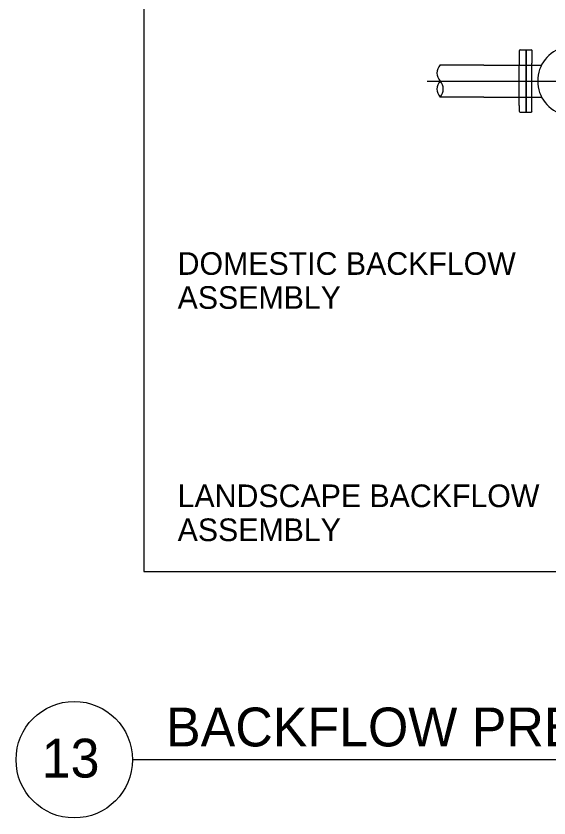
# Model space of a CAD drawing. Extents: x 6710407 to 6714861, y 1868090 to 1871317.
# Drawn here: x 6713621.1 to 6713785.8, y 1869746.3 to 1869994.1 of the extents above; entities that cross this region are included whole.
import ezdxf

# ---------------------------------------------------------------- set-up
doc = ezdxf.new("R2010")
doc.units = 0
doc.layers.add('Nongeo Data(60)', color=7, linetype='Continuous')

msp = doc.modelspace()

# ---------------------------------------------------------------- linework, layer by layer
at = {"layer": 'Nongeo Data(60)'}
for p, q in [((6713660.63, 1870143.75), (6713660.63, 1869916.69)), ((6713776.61, 1869983.35), (6713776.61, 1869978.96)), ((6713776.89, 1869983.63), (6713778.63, 1869983.63)), ((6713778.63, 1869983.63), (6713778.63, 1869969.31)), ((6713778.76, 1869983.62), (6713778.76, 1869969.61)), ((6713778.76, 1869983.62), (6713780.31, 1869983.62)), ((6713780.56, 1869983.37), (6713780.56, 1869979.47)), ((6713765.65, 1869978.93), (6713752.16, 1869978.93)), ((6713765.65, 1869978.93), (6713783.53, 1869978.93)), ((6713776.61, 1869966.46), (6713776.61, 1869978.96)), ((6713780.56, 1869968.49), (6713780.56, 1869979.47)), ((6713748.2, 1869973.99), (6713995.63, 1869973.99)), ((6713765.65, 1869969.02), (6713752.16, 1869969.02)), ((6713765.65, 1869969.02), (6713783.54, 1869969.02)), ((6713778.63, 1869969.31), (6713778.63, 1869964.34)), ((6713778.76, 1869969.61), (6713778.76, 1869964.35)), ((6713780.56, 1869964.6), (6713780.56, 1869968.5)), ((6713776.61, 1869966.46), (6713776.61, 1869964.62)), ((6713776.89, 1869964.34), (6713778.63, 1869964.34)), ((6713778.76, 1869964.35), (6713780.31, 1869964.35)), ((6713660.63, 1869916.69), (6713660.63, 1869822.47)), ((6713660.63, 1869822.47), (6714082.91, 1869822.47)), ((6714108.97, 1869764.3), (6713657.08, 1869764.3))]:
    msp.add_line(p, q, dxfattribs=at)
msp.add_circle((6713639.08, 1869764.3), 18, dxfattribs=at)
for centre, radius, start, end in [((6713793.04, 1869973.99), 10.72, 27.5041, 332.4289), ((6713776.89, 1869983.35), 0.279, 90, 180), ((6713780.31, 1869983.37), 0.257, 0, 90), ((6713754.77, 1869976.46), 3.6, 136.5226, 223.5571), ((6713754.78, 1869971.5), 3.6, 136.461, 223.4594), ((6713749.56, 1869971.5), 3.59, 316.3237, 43.5967), ((6713776.89, 1869964.62), 0.279, 180, 270), ((6713780.31, 1869964.6), 0.257, 270, 0)]:
    msp.add_arc(centre, radius, start, end, dxfattribs=at)

# ---------------------------------------------------------------- texts
for s, height, p in [('DOMESTIC BACKFLOW', 7, (6713671.03, 1869914.1)), ('ASSEMBLY', 7, (6713671.03, 1869903.6)), ('LANDSCAPE BACKFLOW', 7, (6713671.03, 1869842.33)), ('ASSEMBLY', 7, (6713671.03, 1869831.83)), ('BACKFLOW PREVENTER CONCRETE SLAB', 12, (6713667.44, 1869768.4)), ('13', 12, (6713629.03, 1869758.78))]:
    msp.add_text(s, height=height, dxfattribs=at).set_placement(p)

doc.saveas('drawing.dxf')
